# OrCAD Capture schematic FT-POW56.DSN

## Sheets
1 INDEX: title: 01-INDEX; rev: 1.0
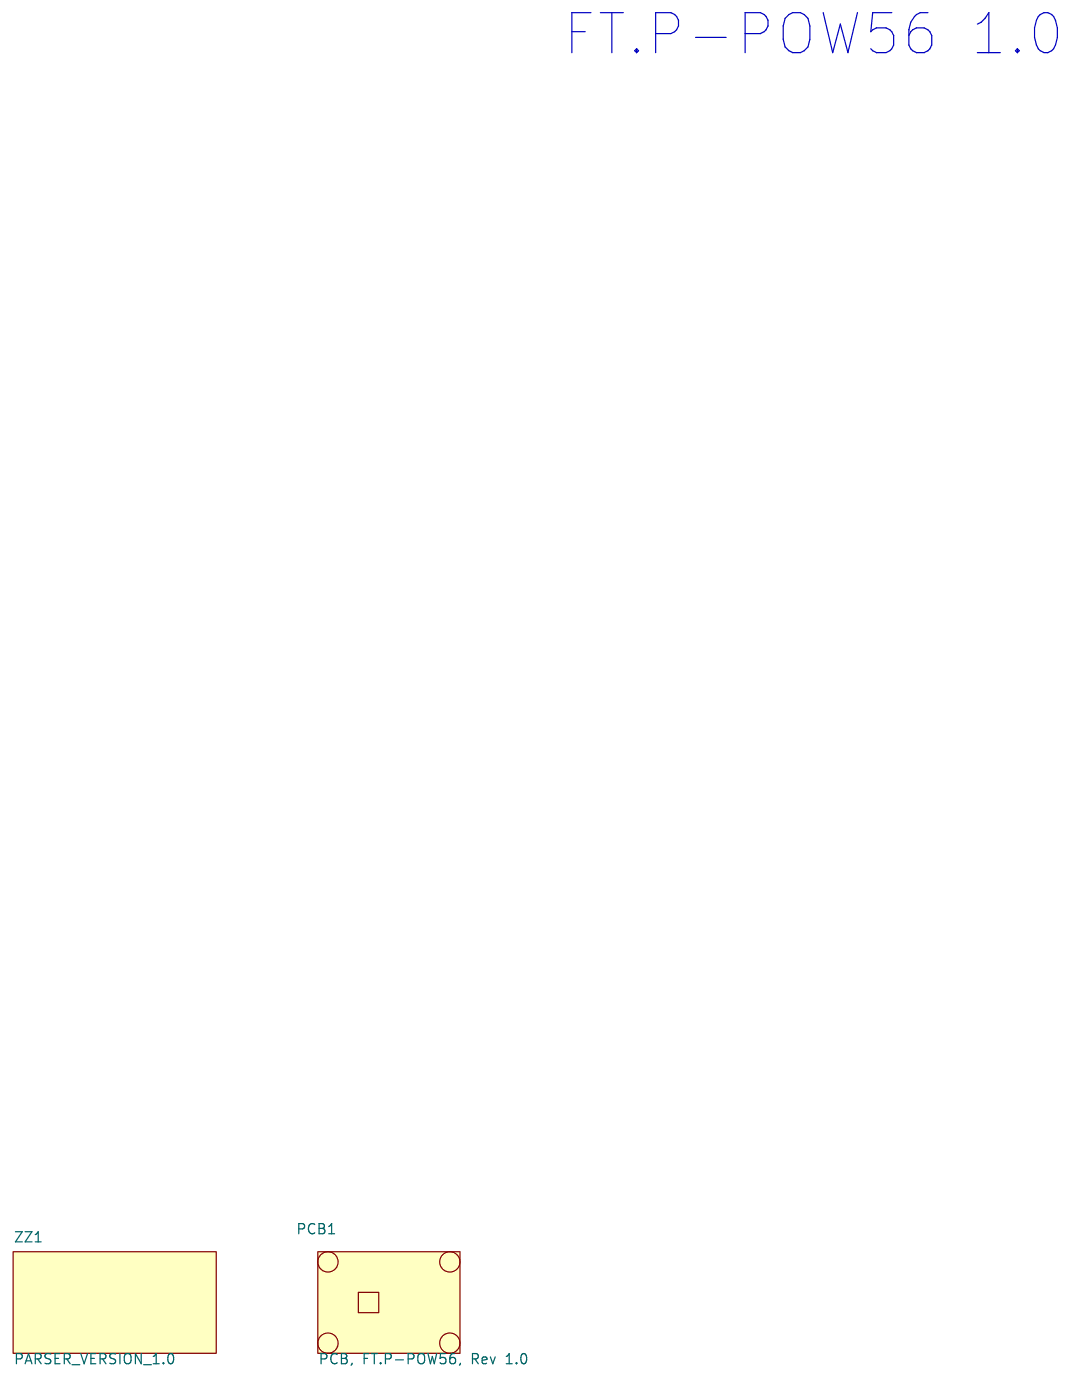
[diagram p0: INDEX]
2 POWER: size A3; title: 02-POWER
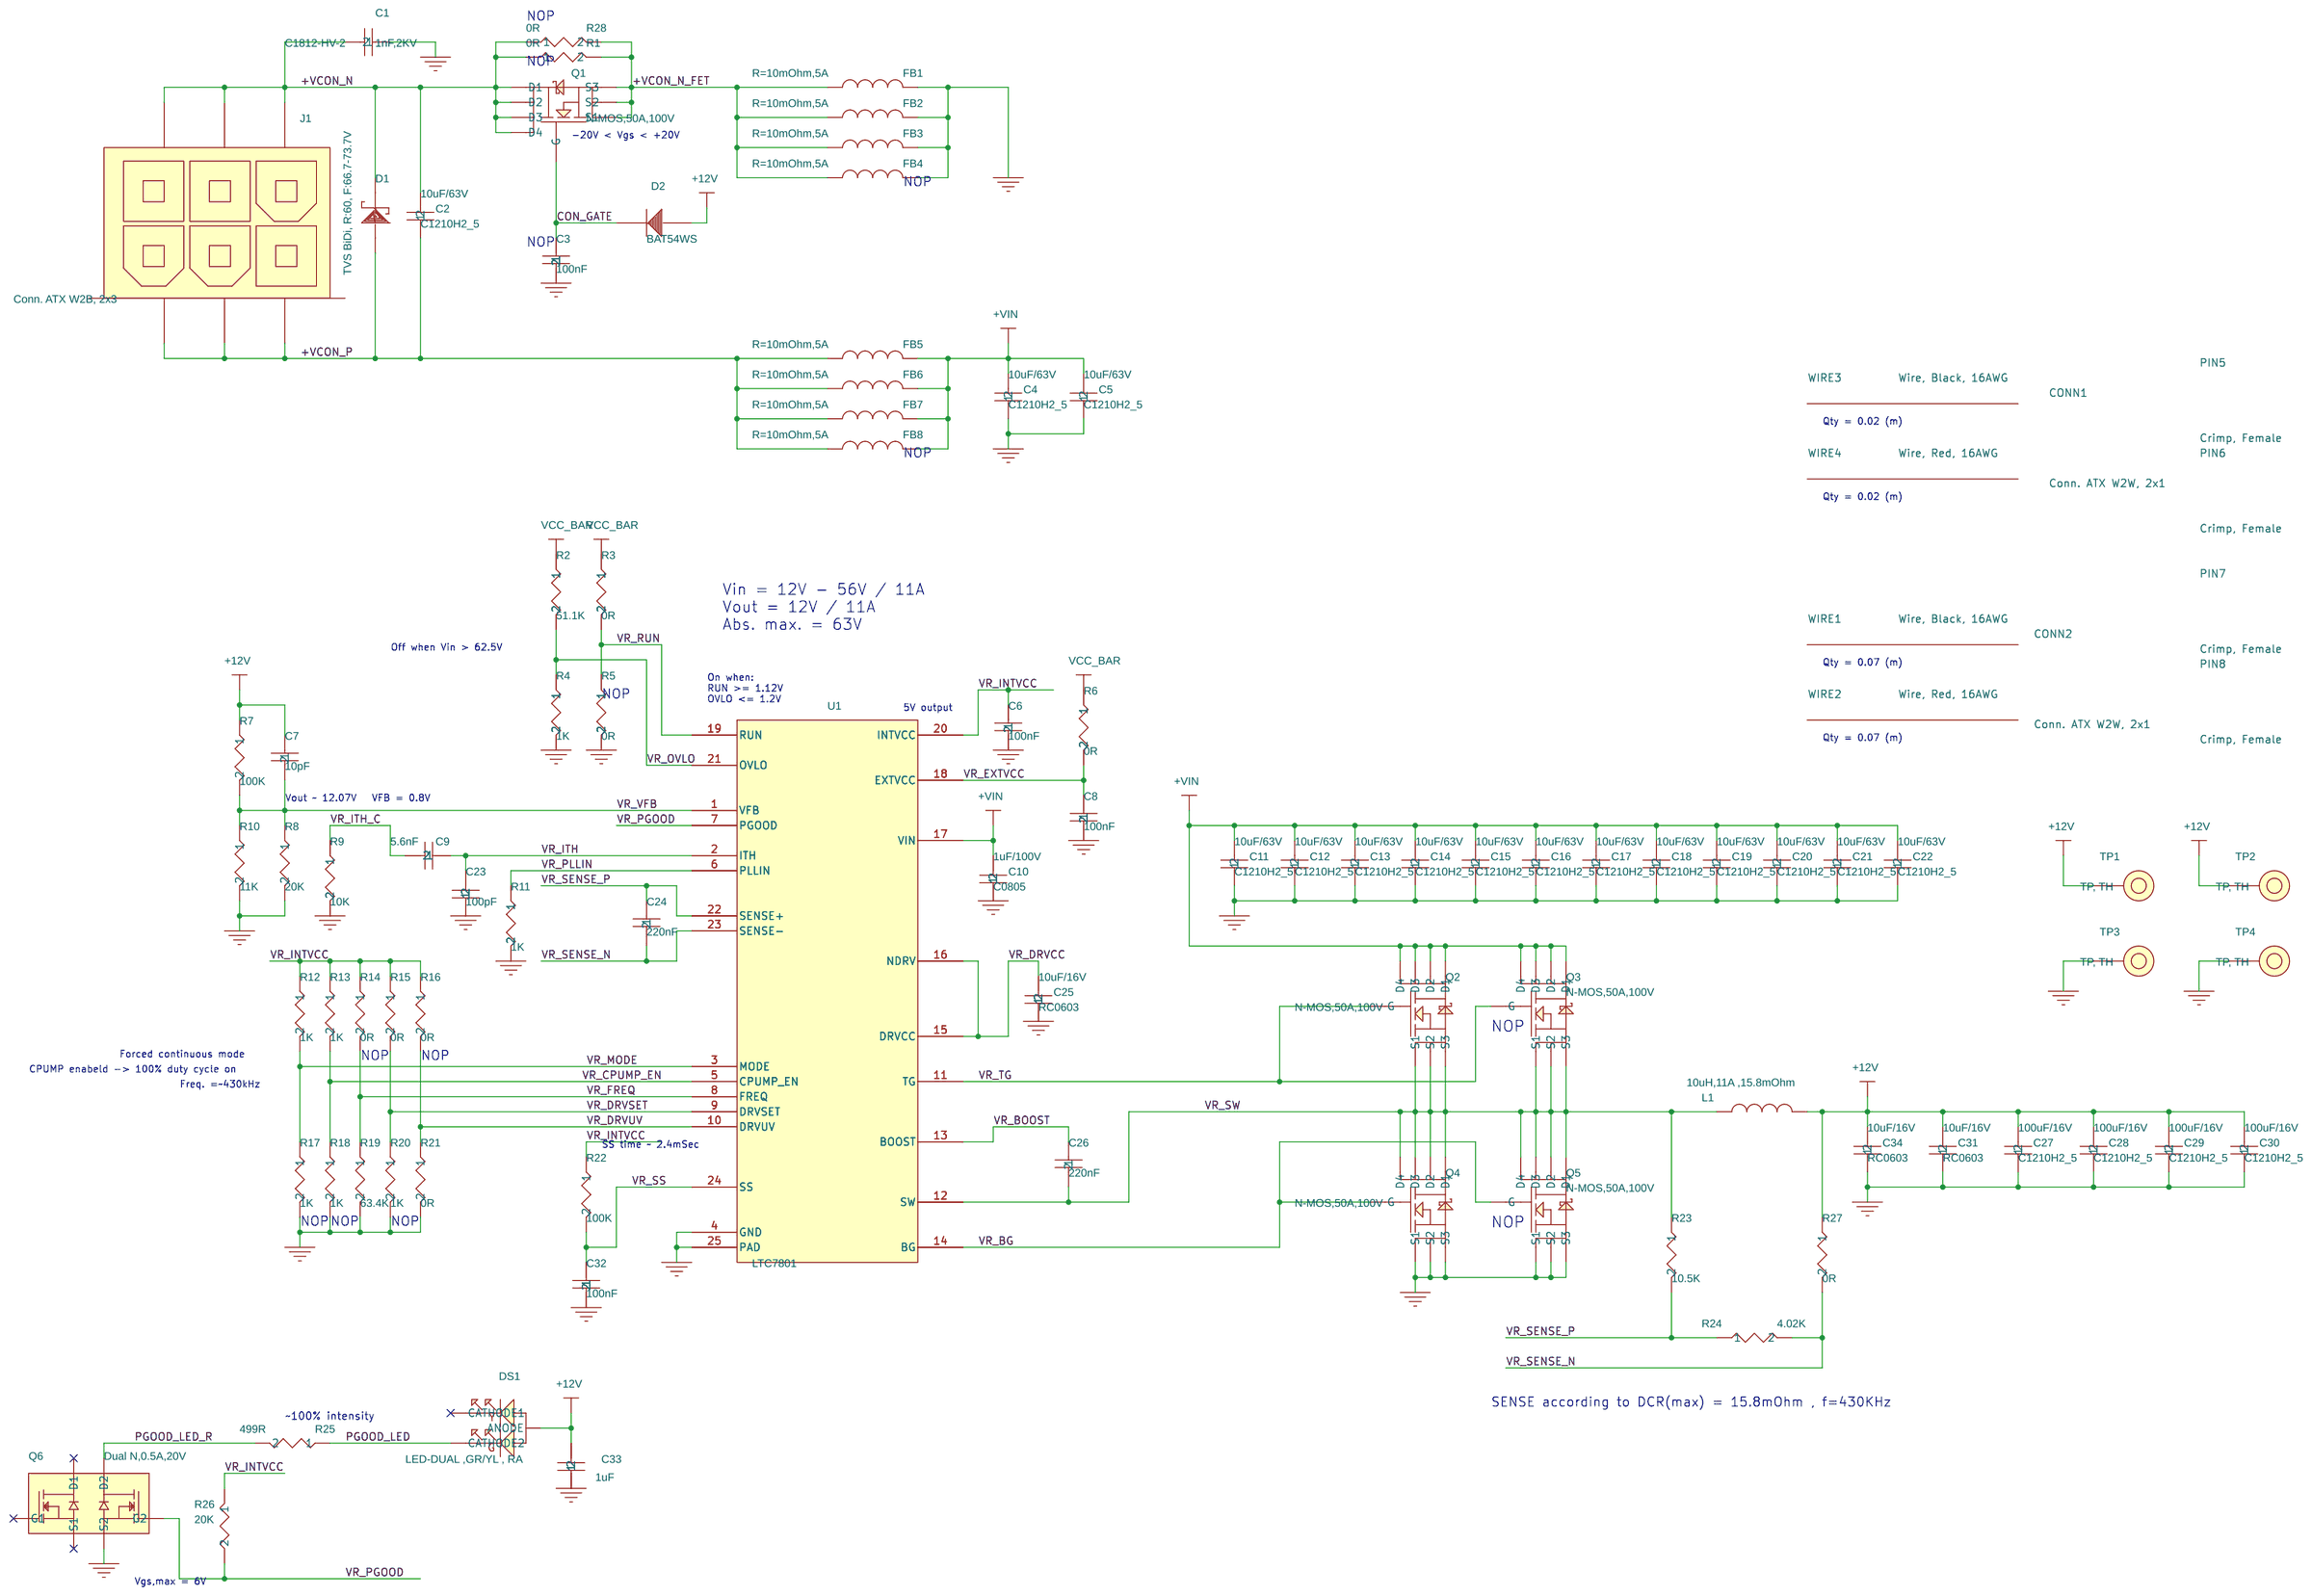
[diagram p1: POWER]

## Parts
sheet INDEX
PCB1  PCB, FT.P-POW56, Rev 1.0
ZZ1  PARSER_VERSION_1.0
sheet POWER
C1  1nF,2KV  [C1812-HV-2]
C2  10uF/63V  [C1210H2_5]
C3  100nF  [RC0402]
C4  10uF/63V  [C1210H2_5]
C5  10uF/63V  [C1210H2_5]
C6  100nF  [RC0402]
C7  10pF  [RC0402]
C8  100nF  [RC0402]
C9  5.6nF  [RC0402]
C10  1uF/100V  [C0805]
C11  10uF/63V  [C1210H2_5]
C12  10uF/63V  [C1210H2_5]
C13  10uF/63V  [C1210H2_5]
C14  10uF/63V  [C1210H2_5]
C15  10uF/63V  [C1210H2_5]
C16  10uF/63V  [C1210H2_5]
C17  10uF/63V  [C1210H2_5]
C18  10uF/63V  [C1210H2_5]
C19  10uF/63V  [C1210H2_5]
C20  10uF/63V  [C1210H2_5]
C21  10uF/63V  [C1210H2_5]
C22  10uF/63V  [C1210H2_5]
C23  100pF  [RC0402]
C24  220nF  [RC0402]
C25  10uF/16V  [RC0603]
C26  220nF  [RC0402]
C27  100uF/16V  [C1210H2_5]
C28  100uF/16V  [C1210H2_5]
C29  100uF/16V  [C1210H2_5]
C30  100uF/16V  [C1210H2_5]
C31  10uF/16V  [RC0603]
C32  100nF  [RC0402]
C33  1uF  [RC0402]
C34  10uF/16V  [RC0603]
CONN1  Conn. ATX W2W, 2x1
CONN2  Conn. ATX W2W, 2x1
D1  TVS BiDi, R:60, F:66.7-73.7V  [DO-214AC]
D2  BAT54WS  [SOD-323]
DS1  LED-DUAL ,GR/YL , RA  [LED-Bi-3x1RASM]
FB1  R=10mOhm,5A  [FB0603]
FB2  R=10mOhm,5A  [FB0603]
FB3  R=10mOhm,5A  [FB0603]
FB4  R=10mOhm,5A  [FB0603]
FB5  R=10mOhm,5A  [FB0603]
FB6  R=10mOhm,5A  [FB0603]
FB7  R=10mOhm,5A  [FB0603]
FB8  R=10mOhm,5A  [FB0603]
J1  Conn. ATX W2B, 2x3  [TBD]
L1  10uH,11A ,15.8mOhm  [IND14x13x7]
PIN5  Crimp, Female
PIN6  Crimp, Female
PIN7  Crimp, Female
PIN8  Crimp, Female
Q1  N-MOS,50A,100V  [PowerpakSO-8]
Q2  N-MOS,50A,100V  [PowerpakSO-8]
Q3  N-MOS,50A,100V  [PowerpakSO-8]
Q4  N-MOS,50A,100V  [PowerpakSO-8]
Q5  N-MOS,50A,100V  [PowerpakSO-8]
Q6  Dual N,0.5A,20V  [SOT-563-6]
R1  0R  [RC0402]
R2  51.1K  [RC0402]
R3  0R  [RC0402]
R4  1K  [RC0402]
R5  0R  [RC0402]
R6  0R  [RC0402]
R7  100K  [RC0402]
R8  20K  [RC0402]
R9  10K  [RC0402]
R10  11K  [RC0402]
R11  1K  [RC0402]
R12  1K  [RC0402]
R13  1K  [RC0402]
R14  0R  [RC0402]
R15  0R  [RC0402]
R16  0R  [RC0402]
R17  1K  [RC0402]
R18  1K  [RC0402]
R19  63.4K  [RC0402]
R20  1K  [RC0402]
R21  0R  [RC0402]
R22  100K  [RC0402]
R23  10.5K  [RC0402]
R24  4.02K  [RC0402]
R25  499R  [RC0402]
R26  20K  [RC0402]
R27  0R  [RC0402]
R28  0R  [RC0402]
TP1  TP, TH  [TPRTH2m]
TP2  TP, TH  [TPRTH2m]
TP3  TP, TH  [TPRTH2m]
TP4  TP, TH  [TPRTH2m]
U1  LTC7801  [MO-220WGHD-1]
WIRE1  Wire, Black, 16AWG
WIRE2  Wire, Red, 16AWG
WIRE3  Wire, Black, 16AWG
WIRE4  Wire, Red, 16AWG

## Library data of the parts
PCB1 = SBC-iHSW_Rev_1.0: CLABCONF0: FT.P-POW56; P/N: 188C03600U
ZZ1 = PARSER_VERSION_1.0: CLABCONF0: FT.P-POW56
C1 = 100nF,_10V,_X7R,_10%,_0402_16: CLABCONF0: FT.P-POW56; P/N: 151J10250S
C2 = 100nF,_10V,_X7R,_10%,_0402_1: CLABCONF0: FT.P-POW56; P/N: 151E10680S
C3 = 15pF,_50V,_NPO,_5%,_0402_8: CLABCONF0: NOP; P/N: 151C10400S
C4 = 100nF,_10V,_X7R,_10%,_0402_23: CLABCONF0: FT.P-POW56; P/N: 151E10680S
C5 = 100nF,_10V,_X7R,_10%,_0402_15: CLABCONF0: FT.P-POW56; P/N: 151E10680S
C6 = 15pF,_50V,_NPO,_5%,_0402_9: CLABCONF0: FT.P-POW56; P/N: 151C10400S
C7 = 15pF,_50V,_NPO,_5%,_0402_7: CLABCONF0: FT.P-POW56; P/N: 151D10000S
C8 = 15pF,_50V,_NPO,_5%,_0402: CLABCONF0: FT.P-POW56; P/N: 151C10400S
C9 = 15pF,_50V,_NPO,_5%,_0402_5: CLABCONF0: FT.P-POW56; P/N: 151C56200S
C10 = 100nF,_10V,_X7R,_10%,_0402: CLABCONF0: FT.P-POW56; P/N: 151E10520S
C11 = 100nF,_10V,_X7R,_10%,_0402_20: CLABCONF0: FT.P-POW56; P/N: 151E10680S
C12 = 100nF,_10V,_X7R,_10%,_0402_18: CLABCONF0: FT.P-POW56; P/N: 151E10680S
C13 = 100nF,_10V,_X7R,_10%,_0402_10: CLABCONF0: FT.P-POW56; P/N: 151E10680S
C14 = 100nF,_10V,_X7R,_10%,_0402_5: CLABCONF0: FT.P-POW56; P/N: 151E10680S
C15 = 100nF,_10V,_X7R,_10%,_0402_2: CLABCONF0: FT.P-POW56; P/N: 151E10680S
C16 = 100nF,_10V,_X7R,_10%,_0402_19: CLABCONF0: FT.P-POW56; P/N: 151E10680S
C17 = 100nF,_10V,_X7R,_10%,_0402_11: CLABCONF0: FT.P-POW56; P/N: 151E10680S
C18 = 100nF,_10V,_X7R,_10%,_0402_6: CLABCONF0: FT.P-POW56; P/N: 151E10680S
C19 = 100nF,_10V,_X7R,_10%,_0402_3: CLABCONF0: FT.P-POW56; P/N: 151E10680S
C20 = 100nF,_10V,_X7R,_10%,_0402_22: CLABCONF0: FT.P-POW56; P/N: 151E10680S
C21 = 100nF,_10V,_X7R,_10%,_0402_14: CLABCONF0: FT.P-POW56; P/N: 151E10680S
C22 = 100nF,_10V,_X7R,_10%,_0402_7: CLABCONF0: FT.P-POW56; P/N: 151E10680S
C23 = 15pF,_50V,_NPO,_5%,_0402_6: CLABCONF0: FT.P-POW56; P/N: 151D10100S
C24 = 15pF,_50V,_NPO,_5%,_0402_2: CLABCONF0: FT.P-POW56; P/N: 151C22400S
C25 = 100nF,_10V,_X7R,_10%,_0402_9: CLABCONF0: FT.P-POW56; P/N: 151C10610S
C26 = 15pF,_50V,_NPO,_5%,_0402_1: CLABCONF0: FT.P-POW56; P/N: 151C22400S
C27 = 100nF,_10V,_X7R,_10%,_0402_21: CLABCONF0: FT.P-POW56; P/N: 151C10780S
C28 = 100nF,_10V,_X7R,_10%,_0402_12: CLABCONF0: FT.P-POW56; P/N: 151C10780S
C29 = 100nF,_10V,_X7R,_10%,_0402_8: CLABCONF0: FT.P-POW56; P/N: 151C10780S
C30 = 100nF,_10V,_X7R,_10%,_0402_4: CLABCONF0: FT.P-POW56; P/N: 151C10780S
C31 = 100nF,_10V,_X7R,_10%,_0402_17: CLABCONF0: FT.P-POW56; P/N: 151C10610S
C32 = 15pF,_50V,_NPO,_5%,_0402_4: CLABCONF0: FT.P-POW56; P/N: 151B10400S
C33 = 15pF,_50V,_NPO,_5%,_0402_3: CLABCONF0: FT.P-POW56; P/N: 151C10500S
C34 = 100nF,_10V,_X7R,_10%,_0402_13: CLABCONF0: FT.P-POW56; P/N: 151C10610S
CONN1 CONN2 = Conn._ATX_W2W,_2x1: CLABCONF0: FT.P-POW56; P/N: 180G00201
D1 = Diode_,MBRS340_,3A_0: CLABCONF0: FT.P-POW56; P/N: 132D10110S
D2 = BAT54WS: CLABCONF0: FT.P-POW56
DS1 = LED,_Dual,ip_3x1mm,_R_A,_G_Y: CLABCONF0: FT.P-POW56
FB1 = Ferrite_bead_,_120_Ohm@3A_1: CLABCONF0: FT.P-POW56; P/N: 147D30000S
FB2 = Ferrite_bead_,_120_Ohm@3A_4: CLABCONF0: FT.P-POW56; P/N: 147D30000S
FB3 = Ferrite_bead_,_120_Ohm@3A_2: CLABCONF0: FT.P-POW56; P/N: 147D30000S
FB4 = Ferrite_bead_,_120_Ohm@3A_3: CLABCONF0: NOP; P/N: 147D30000S
FB5 = Ferrite_bead_,_120_Ohm@3A: CLABCONF0: FT.P-POW56; P/N: 147D30000S
FB6 = Ferrite_bead_,_120_Ohm@3A_7: CLABCONF0: FT.P-POW56; P/N: 147D30000S
FB7 = Ferrite_bead_,_120_Ohm@3A_6: CLABCONF0: FT.P-POW56; P/N: 147D30000S
FB8 = Ferrite_bead_,_120_Ohm@3A_5: CLABCONF0: NOP; P/N: 147D30000S
J1 = Conn._ATX_W2B,_2x3: CLABCONF0: FT.P-POW56; P/N: 182K00602
L1 = Ind.,_0.36uH_36A_0.82mOhm: CLABCONF0: FT.P-POW56; P/N: 147A10003S
PIN5-PIN8 = Crimp,_Female: CLABCONF0: FT.P-POW56; P/N: 197B00500
Q1 Q2 Q4 = FDMS7682: CLABCONF0: FT.P-POW56; P/N: 131D10120S
Q3 Q5 = FDMS7682: CLABCONF0: NOP; P/N: 131D10120S
Q6 = DUAL_N-MOSFET,_0.5A_20V: CLABCONF0: FT.P-POW56
R1 = 348R,1%,0402,1_16W_19: CLABCONF0: NOP; P/N: 161C00005S
R2 = 348R,1%,0402,1_16W_16: CLABCONF0: FT.P-POW56; P/N: 161C51121S
R3 = 348R,1%,0402,1_16W_25: CLABCONF0: FT.P-POW56; P/N: 161C00005S
R4 = 348R,1%,0402,1_16W_2: CLABCONF0: FT.P-POW56; P/N: 161C10011S
R5 = 348R,1%,0402,1_16W_18: CLABCONF0: NOP; P/N: 161C00005S
R6 = 348R,1%,0402,1_16W_23: CLABCONF0: FT.P-POW56; P/N: 161C00005S
R7 = 348R,1%,0402,1_16W_3: CLABCONF0: FT.P-POW56; P/N: 161C10031S
R8 = 348R,1%,0402,1_16W_20: CLABCONF0: FT.P-POW56; P/N: 161C20021S
R9 = 348R,1%,0402,1_16W_26: CLABCONF0: FT.P-POW56; P/N: 161C10021S
R10 = 348R,1%,0402,1_16W_12: CLABCONF0: FT.P-POW56; P/N: 161C11021S
R11 = 348R,1%,0402,1_16W_15: CLABCONF0: FT.P-POW56; P/N: 161C10011S
R12 = 348R,1%,0402,1_16W_1: CLABCONF0: FT.P-POW56; P/N: 161C10011S
R13 = 348R,1%,0402,1_16W_9: CLABCONF0: FT.P-POW56; P/N: 161C10011S
R14 = 348R,1%,0402,1_16W_10: CLABCONF0: NOP; P/N: 161C00005S
R15 = 348R,1%,0402,1_16W_4: CLABCONF0: FT.P-POW56; P/N: 161C00005S
R16 = 348R,1%,0402,1_16W_14: CLABCONF0: NOP; P/N: 161C00005S
R17 = 348R,1%,0402,1_16W_11: CLABCONF0: NOP; P/N: 161C10011S
R18 = 348R,1%,0402,1_16W_21: CLABCONF0: NOP; P/N: 161C10011S
R19 = 348R,1%,0402,1_16W_6: CLABCONF0: FT.P-POW56; P/N: 161C63421S
R20 = 348R,1%,0402,1_16W: CLABCONF0: NOP; P/N: 161C10011S
R21 = 348R,1%,0402,1_16W_24: CLABCONF0: FT.P-POW56; P/N: 161C00005S
R22 = 348R,1%,0402,1_16W_17: CLABCONF0: FT.P-POW56; P/N: 161C20031S
R23 = 348R,1%,0402,1_16W_5: CLABCONF0: FT.P-POW56; P/N: 161C10521S
R24 = 348R,1%,0402,1_16W_8: CLABCONF0: FT.P-POW56; P/N: 161C40211S
R25 = 1M_,5%,_0402: CLABCONF0: FT.P-POW56; P/N: 161C49901S
R26 = 348R,1%,0402,1_16W_22: CLABCONF0: FT.P-POW56; P/N: 161C20021S
R27 = 348R,1%,0402,1_16W_13: CLABCONF0: FT.P-POW56; P/N: 161C00005S
R28 = 348R,1%,0402,1_16W_7: CLABCONF0: NOP; P/N: 161C00005S
TP1-TP4 = TestPoint_0: CLABCONF0: NOP; P/N: 188Z01380
U1 = LTC7801: CLABCONF0: FT.P-POW56; P/N: 123V60000S
WIRE1 = Wire,_Black,_16AWG: CLABCONF0: 0.07#409M02001 = FT.P-POW56; CLABUNIT: m; P/N: 409M02001
WIRE2 = Wire,_Black,_16AWG: CLABCONF0: 0.07#409M03001 = FT.P-POW56; CLABUNIT: m; P/N: 409M03001
WIRE3 = Wire,_Black,_16AWG: CLABCONF0: 0.02#409M02001 = FT.P-POW56; CLABUNIT: m; P/N: 409M02001
WIRE4 = Wire,_Black,_16AWG: CLABCONF0: 0.02#409M03001 = FT.P-POW56; CLABUNIT: m; P/N: 409M03001

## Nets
+12V: C7.1 C27.2 C28.2 C29.2 C30.2 C31.2 C33.2 C34.2 D2.ANODE DS1.A(ANODE) L1.2 R6.1 R7.1 R27.1 TP1.1 TP2.1
+VIN: C4.2 C5.2 C10.2 C11.2 C12.2 C13.2 C14.2 C15.2 C16.2 C17.2 C18.2 C19.2 C20.2 C21.2 C22.2 FB5.2 FB6.2 FB7.2 FB8.2 Q2.5(D1) Q2.6(D2) Q2.7(D3) Q2.8(D4) Q3.5(D1) Q3.6(D2) Q3.7(D3) Q3.8(D4) R2.1 R3.1 U1.17(VIN)
GND: C1.1 C3.2 C4.1 C5.1 C6.2 C8.2 C10.1 C11.1 C12.1 C13.1 C14.1 C15.1 C16.1 C17.1 C18.1 C19.1 C20.1 C21.1 C22.1 C23.1 C25.1 C27.1 C28.1 C29.1 C30.1 C31.1 C32.2 C33.1 C34.1 FB1.2 FB2.2 FB3.2 FB4.2 Q4.1(S1) Q4.2(S2) Q4.3(S3) Q5.1(S1) Q5.2(S2) Q5.3(S3) Q6.4(S2) R4.2 R5.2 R8.2 R9.2 R10.2 R11.2 R17.2 R18.2 R19.2 R20.2 R21.2 TP3.1 TP4.1 U1.4(GND) U1.25(PAD)
+VCON_N: C1.2 C2.2 D1.CATHODE J1.4 J1.5 J1.6 Q1.5(D1) Q1.6(D2) Q1.7(D3) Q1.8(D4) R1.1 R28.1
+VCON_N_FET: FB1.1 FB2.1 FB3.1 FB4.1 Q1.1(S1) Q1.2(S2) Q1.3(S3) R1.2 R28.2
+VCON_P: C2.1 D1.ANODE FB5.1 FB6.1 FB7.1 FB8.1 J1.1 J1.2 J1.3
CON_GATE: C3.1 D2.CATHODE Q1.4(G)
PGOOD_LED: DS1.C2(CATHODE2) R25.1
PGOOD_LED_R: Q6.3(D2) R25.2
VR_BG: Q4.4(G) Q5.4(G) U1.14(BG)
VR_BOOST: C26.1 U1.13(BOOST)
VR_CPUMP_EN: R13.2 R18.1 U1.5(CPUMP_EN)
VR_DRVCC: C25.2 U1.15(DRVCC) U1.16(NDRV)
VR_DRVSET: R15.2 R20.1 U1.9(DRVSET)
VR_DRVUV: R16.2 R21.1 U1.10(DRVUV)
VR_EXTVCC: C8.1 R6.2 U1.18(EXTVCC)
VR_FREQ: R14.2 R19.1 U1.8(FREQ)
VR_INTVCC: C6.1 R12.1 R13.1 R14.1 R15.1 R16.1 R22.1 R26.1 U1.20(INTVCC)
VR_ITH: C9.1 C23.2 U1.2(ITH)
VR_ITH_C: C9.2 R9.1
VR_MODE: R12.2 R17.1 U1.3(MODE)
VR_OVLO: R2.2 R4.1 U1.21(OVLO)
VR_PGOOD: Q6.5(G2) R26.2 U1.7(PGOOD)
VR_PLLIN: R11.1 U1.6(PLLIN)
VR_RUN: R3.2 R5.1 U1.19(RUN)
VR_SENSE_N: C24.2 R24.2 R27.2 U1.23(SENSE-)
VR_SENSE_P: C24.1 R23.2 R24.1 U1.22(SENSE+)
VR_SS: C32.1 R22.2 U1.24(SS)
VR_SW: C26.2 L1.1 Q2.1(S1) Q2.2(S2) Q2.3(S3) Q3.1(S1) Q3.2(S2) Q3.3(S3) Q4.5(D1) Q4.6(D2) Q4.7(D3) Q4.8(D4) Q5.5(D1) Q5.6(D2) Q5.7(D3) Q5.8(D4) R23.1 U1.12(SW)
VR_TG: Q2.4(G) Q3.4(G) U1.11(TG)
VR_VFB: C7.2 R7.2 R8.1 R10.1 U1.1(VFB)

Not connected (* = marked no-connect by the designer): DS1 C1(CATHODE1)*; Q6 1(S1)* 2(G1)* 6(D1)*

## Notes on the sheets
sheet 1
- FT.P-POW56 1.0
sheet 2
- NOP
- NOP
- -20V < Vgs < +20V
- NOP
- NOP
- Qty = 0.02 (m)
- NOP
- Qty = 0.02 (m)
- Vin = 12V - 56V / 11A
  Vout = 12V / 11A
  Abs. max. = 63V
- Off when Vin > 62.5V
- Qty = 0.07 (m)
- On when:
  RUN >= 1.12V
  OVLO <= 1.2V
- NOP
- 5V output
- Qty = 0.07 (m)
- Vout ~ 12.07V   VFB = 0.8V
- NOP
- Forced continuous mode
- NOP
- NOP
- CPUMP enabeld -> 100% duty cycle on
- Freq. =~430kHz
- SS time ~ 2.4mSec
- NOP
- NOP
- NOP
- NOP
- SENSE according to DCR(max) = 15.8mOhm , f=430KHz
- ~100% intensity
- Vgs,max = 6V
